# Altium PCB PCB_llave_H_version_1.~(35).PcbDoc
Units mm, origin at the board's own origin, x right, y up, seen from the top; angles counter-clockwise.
Board outline 232.16 x 155.45 mm, 2 copper layers (Top Layer, Bottom Layer); 60 components, 32 nets, 175 pads, 0 vias.
Unrouted connection lines stored in the file: 67.
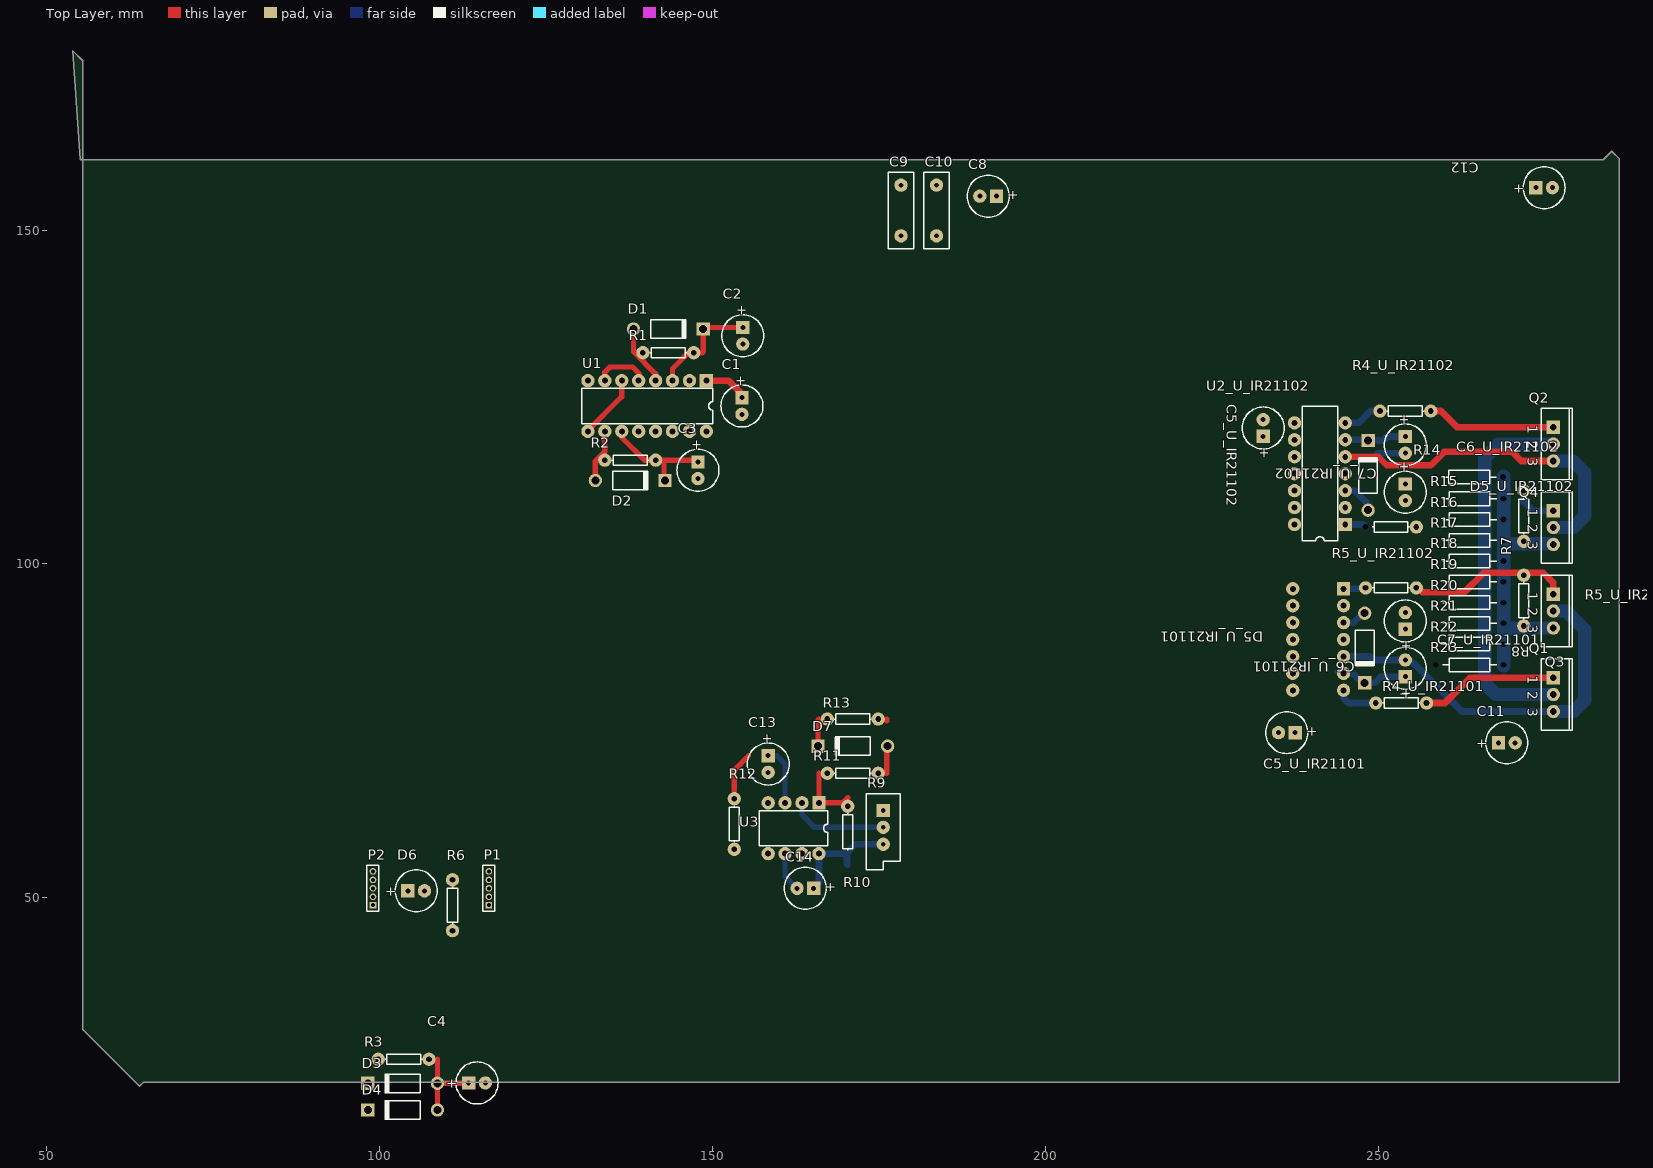
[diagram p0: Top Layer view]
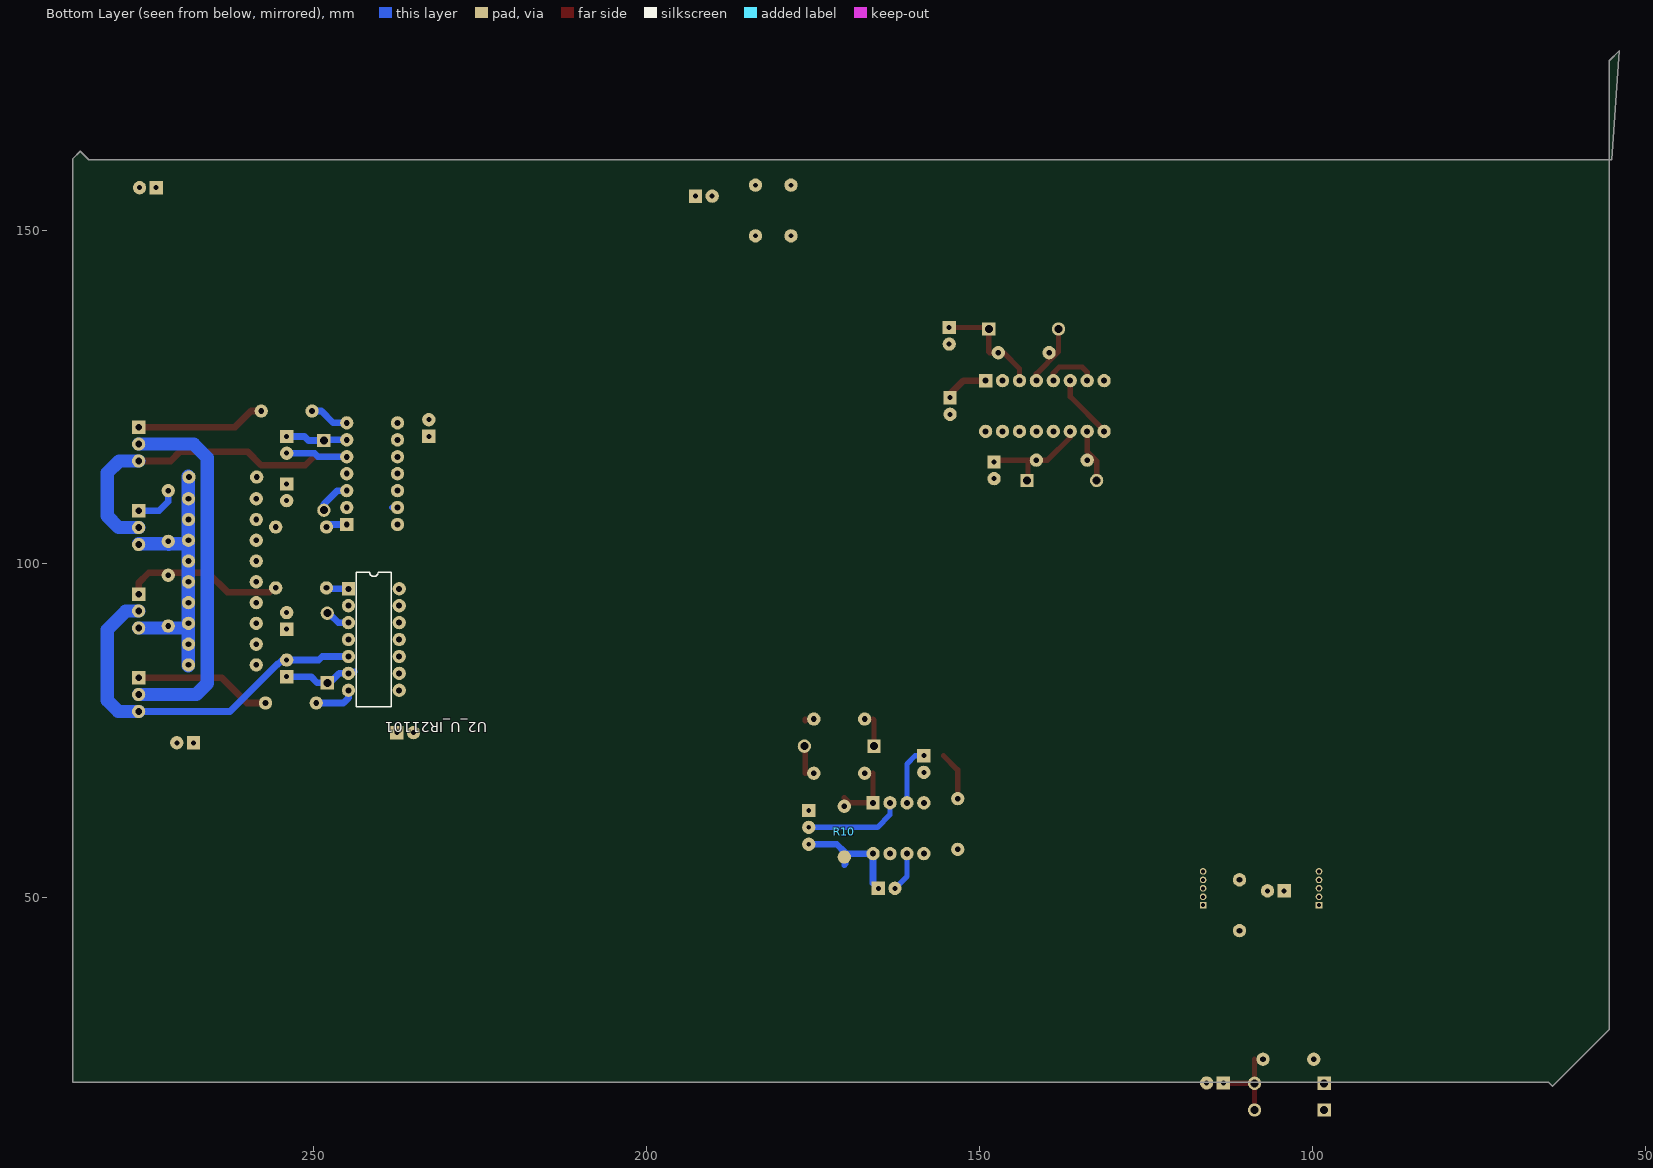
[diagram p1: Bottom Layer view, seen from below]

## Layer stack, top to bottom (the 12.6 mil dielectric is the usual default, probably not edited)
Top Layer: signal copper 0.0356
Dielectric: dielectric 0.32, FR-4, Dk 4.8
Bottom Layer: signal copper 0.0356

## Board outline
53.975,177.038 55.499,175.514 55.499,30.099 64.008,21.59 64.643,22.225 286.131,22.225 286.131,160.782 284.988,161.925 283.718,160.655 55.118,160.655

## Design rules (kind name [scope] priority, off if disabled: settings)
Clearance [All] p1: gap=0.4
ComponentClearance [All] p1: gap=0.254 collisioncheckmode=2 verticalgap=0.254
PolygonConnect [All] p1: connectstyle=Relief reliefconductorwidth=0.254 reliefentries=4 polygonreliefangle="90 Angle"
RoomDefinition U_IR21102 [InComponentClass('U_IR21102')] p1: confinementstyle=ConfineIn formatcopy=TRUE lockcomponents=FALSE outline 226.949,131.445 260.858,131.445 260.858,95.504 226.949,95.504
RoomDefinition U_Puente_H [InComponentClass('U_Puente_H')] p2: confinementstyle=ConfineOut formatcopy=TRUE lockcomponents=FALSE outline 302.133,128.016 302.133,110.363 311.531,110.363 311.531,128.016
RoomDefinition U_INITShutdown [InComponentClass('U_INITShutdown')] p3: confinementstyle=ConfineIn formatcopy=TRUE lockcomponents=FALSE outline 90.297,32.893 141.097,32.893 141.097,13.97 90.297,13.97
RoomDefinition U_Shutdown [InComponentClass('U_Shutdown')] p4: confinementstyle=ConfineOut formatcopy=TRUE lockcomponents=FALSE outline 142.113,82.931 143.51,82.931 143.51,79.629 142.113,79.629
RoomDefinition Llave_H_esquema [InComponentClass('Llave_H_esquema')] p5: confinementstyle=ConfineIn formatcopy=TRUE lockcomponents=FALSE outline 97.917,40.513 118.237,40.513 118.237,57.531 97.917,57.531
RoomDefinition U_4049 [InComponentClass('U_4049')] p6: confinementstyle=ConfineIn formatcopy=TRUE lockcomponents=FALSE outline 120.904,108.712 162.56,108.712 162.56,141.478 120.904,141.478
RoomDefinition U_IR21101 [InComponentClass('U_IR21101')] p7: confinementstyle=ConfineIn formatcopy=TRUE lockcomponents=FALSE outline 227.203,107.188 260.604,107.188 260.604,66.167 227.203,66.167
RoutingVias [All] p1: holewidth=0.711 width=1.27 viastyle="Through Hole" minholewidth=0.711 minwidth=1.27 maxholewidth=0.711 maxwidth=1.27
SolderMaskExpansion [All] p1: expansion=0.102
TestPointUsage [All] p1: valid=0 allowmultiple=FALSE
Testpoint [All] p1: side=15 testpointundercomponent=TRUE minsize=1.016 maxsize=2.54 preferedsize=1.524 minholesize=0 maxholesize=1.016 preferedholesize=0.813 testpointgrid=0.025 style=1023 order=0-112345678
Width [All] p1: maxlimit=3 minlimit=0.8 preferedwidth=1
18 further rules are at their usual default settings.

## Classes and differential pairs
component class U_INITShutdown: C4 D3 D4 R3
channel class IR2110: U_IR21101 U_IR21102
component class U_Shutdown: C13 C14 D7 R9 R10 R11 R12 R13 R14 R15 R16 R17 R18 R19 R20 R21 R22 R23 U3
component class U_Puente_H: C8 C9 C10 C11 C12 Q1 Q2 Q3 Q4 R7 R8
component class U_IR21102: C5_U_IR21102 C6_U_IR21102 C7_U_IR21102 D5_U_IR21102 R4_U_IR21102 R5_U_IR21102 U2_U_IR21102
component class U_IR21101: C5_U_IR21101 C6_U_IR21101 C7_U_IR21101 D5_U_IR21101 R4_U_IR21101 R5_U_IR21101 U2_U_IR21101
component class U_4049: C1 C2 C3 D1 D2 R1 R2 U1
component class Llave_H_esquema: D6 P1 P2 R6

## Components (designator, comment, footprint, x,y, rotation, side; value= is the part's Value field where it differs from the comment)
C1 "Cap Pol1" CAPPR2.5-6.3X5 154.432,123.698 r270 top
C2 "Cap Pol1" CAPPR2.5-6.3X5 154.559,134.239 r270 top
C3 "Cap Pol1" CAPPR2.5-6.3X5 147.828,114.046 r270 top
C4 "Cap Pol1" CAPPR2.5-6.3X5 114.681,22.098 r0 top
C5_U_IR21101 "Cap Pol1" CAPPR2.5-6.3X5 236.22,74.676 r180 top (schematic designator C5)
C5_U_IR21102 "Cap Pol1" CAPPR2.5-6.3X5 232.664,120.396 r90 top (schematic designator C5)
C6_U_IR21101 "Cap Pol1" CAPPR2.5-6.3X5 254,84.328 r90 top (schematic designator C6)
C6_U_IR21102 "Cap Pol1" CAPPR2.5-6.3X5 254,117.856 r270 top (schematic designator C6)
C7_U_IR21101 "Cap Pol1" CAPPR2.5-6.3X5 254,91.44 r90 top (schematic designator C7)
C7_U_IR21102 "Cap Pol1" CAPPR2.5-6.3X5 254,110.744 r270 top (schematic designator C7)
C8 "Cap Pol1" CAPPR2.5-6.3X5 191.389,155.194 r180 top
C9 "Cap" RAD-0.3 178.308,153.035 r90 top
C10 "Cap" RAD-0.3 183.642,153.035 r90 top
C11 "Cap Pol1" CAPPR2.5-6.3X5 269.24,73.152 r0 top
C12 "Cap Pol1" CAPPR2.5-6.3X5 274.828,156.464 r0 top
C13 "Cap Pol1" CAPPR2.5-6.3X5 158.369,69.957 r270 top
C14 "Cap Pol1" CAPPR2.5-6.3X5 163.957,51.308 r180 top
D1 "Diode" DO-204AL 143.383,135.255 r0 top
D2 "Diode" DO-204AL 137.668,112.522 r0 top
D3 "Diode" DO-204AL 103.505,22.036 r180 top
D4 "Diode" DO-204AL 103.505,18.034 r180 top
D5_U_IR21101 "Diode" DO-204AL 247.904,87.376 r270 top (schematic designator D5)
D5_U_IR21102 "Diode" DO-204AL 248.412,113.284 r90 top (schematic designator D5)
D6 "LED0" CAPPR2.5-6.3X5 105.537,50.927 r0 top
D7 "Diode" DO-204AL 171.069,72.644 r180 top
P1 "MHDR1X5" MHDR1X5 116.459,48.768 r90 top
P2 "MHDR1X5" MHDR1X5 99.06,48.768 r90 top
Q1 "IRF3205" TO-220AB 276.225,80.391 r270 top
Q2 "IRF3205" TO-220AB 276.225,117.983 r270 top
Q3 "IRF3205" TO-220AB 276.225,92.922 r270 top
Q4 "IRF3205" TO-220AB 276.225,105.452 r270 top
R1 "Res2" AXIAL-0.3#1 143.383,131.699 r180 top
R2 "Res2" AXIAL-0.3#1 137.668,115.57 r0 top
R3 "Res2" AXIAL-0.3#1 103.661,25.654 r180 top
R4_U_IR21101 "Res2" AXIAL-0.3#1 253.365,79.121 r0 top (schematic designator R4)
R4_U_IR21102 "Res2" AXIAL-0.3#1 254,122.936 r0 top (schematic designator R4)
R5_U_IR21101 "Res2" AXIAL-0.3#1 251.841,96.393 r0 top (schematic designator R5)
R5_U_IR21102 "Res2" AXIAL-0.3#2 251.841,105.537 r0 top (schematic designator R5)
R6 "Res2" AXIAL-0.3#1 110.998,48.768 r90 top
R7 "Res2" AXIAL-0.3#1 271.78,107.188 r90 top
R8 "Res2" AXIAL-0.3#3 271.78,94.488 r90 top
R9 "RPot" VR5 175.641,60.452 r270 top
R10 "Res2" AXIAL-0.3#4 170.307,59.817 r270 top
R11 "Res2" AXIAL-0.3#1 171.069,68.58 r0 top
R12 "Res2" AXIAL-0.3#1 153.289,60.96 r90 top
R13 "Res2" AXIAL-0.3#1 171.069,76.708 r180 top
R14 "Res2" AXIAL-0.4#1 263.585,113.03 r0 top
R15 "Res2" AXIAL-0.4#1 263.652,109.774 r0 top
R16 "Res2" AXIAL-0.4#1 263.652,106.657 r0 top
R17 "Res2" AXIAL-0.4#1 263.652,103.539 r0 top
R18 "Res2" AXIAL-0.4#1 263.652,100.422 r0 top
R19 "Res2" AXIAL-0.4#1 263.652,97.305 r0 top
R20 "Res2" AXIAL-0.4#2 263.652,94.188 r0 top
R21 "Res2" AXIAL-0.4#2 263.652,91.07 r0 top
R22 "Res2" AXIAL-0.4#2 263.652,87.953 r0 top
R23 "Res2" AXIAL-0.4#2 263.652,84.836 r0 top
U1 "MC54HC4049J" 620-09 140.208,123.698 r180 top
U2_U_IR21101 "IR2110" PDIP14 240.919,88.646 r270 bottom (schematic designator U2)
U2_U_IR21102 "IR2110" PDIP14 241.173,113.538 r90 top (schematic designator U2)
U3 "LM393N" 626-05 162.179,60.325 r180 top

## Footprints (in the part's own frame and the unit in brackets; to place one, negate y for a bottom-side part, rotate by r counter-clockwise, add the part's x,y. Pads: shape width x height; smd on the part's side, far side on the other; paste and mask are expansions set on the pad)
620-09 [mm] "DIP; 16 Leads; Row Spacing 7.62 mm; Pitch 2.54 mm"
  rect 2x2 hole 0.9: 1(-8.89,-3.81)
  round 2 hole 0.9: 2(-6.35,-3.81) 3(-3.81,-3.81) 4(-1.27,-3.81) 5(1.27,-3.81) 6(3.81,-3.81) 7(6.35,-3.81) 8(8.89,-3.81) 9(8.89,3.81) 10(6.35,3.81) 11(3.81,3.81) 12(1.27,3.81) 13(-1.27,3.81) 14(-3.81,3.81) 15(-6.35,3.81) 16(-8.89,3.81)
  silkscreen extent -9.85,-2.65 9.85,2.65
626-05 [mm] "DIP; 8 Leads; Row Spacing 7.62 mm; Pitch 2.54 mm"
  rect 2x2 hole 0.9: 1(-3.81,-3.81)
  round 2 hole 0.9: 2(-1.27,-3.81) 3(1.27,-3.81) 4(3.81,-3.81) 5(3.81,3.81) 6(1.27,3.81) 7(-1.27,3.81) 8(-3.81,3.81)
  silkscreen extent -5.15,-2.65 5.15,2.65
AXIAL-0.3#1 [mm] "Resistor; 2 Leads"
  round 2 hole 0.85: 1(-3.81,0) 2(3.81,0)
  silkscreen extent -2.77,-0.76 2.77,0.76
AXIAL-0.3#2 [mm] "Resistor; 2 Leads"
  round 0 / inner round 0 / far side round 2 hole 0.85: 1(-3.81,0)
  round 2 hole 0.85: 2(3.81,0)
  silkscreen extent -2.77,-0.76 2.77,0.76
AXIAL-0.3#3 [mm] "Resistor; 2 Leads"
  round 2 hole 0.85 paste+0 mask+0.102: 1(-3.81,0)
  round 2 hole 0.85: 2(3.81,0)
  silkscreen extent -2.77,-0.76 2.77,0.76
AXIAL-0.3#4 [mm] "Resistor; 2 Leads"
  round 2 hole 0.85: 1(-3.81,0)
  round 2 smd far side: 2(3.81,0)
  silkscreen extent -2.77,-0.76 2.77,0.76
AXIAL-0.4#1 [mm] "Resistor; 2 Leads"
  round 0 / inner round 0 / far side round 2 hole 0.85: 1(-5.08,0) 2(5.08,0)
  silkscreen extent -4.06,-1.02 4.06,1.02
AXIAL-0.4#2 [mm] "Resistor; 2 Leads"
  round 0 / inner round 0 / far side round 2 hole 0.85: 1(-5.08,0)
  round 0 / inner round 0 / far side round 2 hole 0.85 unplated: 2(5.08,0)
  silkscreen extent -4.06,-1.02 4.06,1.02
CAPPR2.5-6.3X5 [mm] "Capacitor, Electrolytic, Radial; Body 6.3 x 5 mm (Dia.xH typ); Pin Spacing 2.5 mm (typ)"
  rect 2x2 hole 0.75: 1(-1.25,0)
  round 2 hole 0.75: 2(1.25,0)
  silkscreen extent -3.15,-3.15 3.15,3.15
DO-204AL [mm] "Diode, Axial; Body 5.2 x 2.7 mm (LxDia. max), Lead Dia. 0.86 mm (max)"
  round 2 hole 1.2: 1(-5.23,0)
  rect 2x2 hole 1.2: 2(5.23,0)
  silkscreen extent -2.65,-1.4 2.75,1.4
MHDR1X5 [mm] "Connector; Header; 5 Position"
  rect 1x1 hole 0.6: 1(0,0)
  round 1 hole 0.6: 2(1.27,0) 3(2.54,0) 4(3.81,0) 5(5.08,0)
  silkscreen extent -0.9,-0.9 5.98,0.9
PDIP14 [mm] "DIP; 14 Leads; Row Spacing 7.62 mm; Pitch 2.54 mm"
  rect 2x2 hole 0.9: 1(-7.62,-3.81)
  round 2 hole 0.9: 2(-5.08,-3.81) 3(-2.54,-3.81) 4(0,-3.81) 5(2.54,-3.81) 6(5.08,-3.81) 7(7.62,-3.81) 8(7.62,3.81) 9(5.08,3.81) 10(2.54,3.81) 11(0,3.81) 12(-2.54,3.81) 13(-5.08,3.81) 14(-7.62,3.81)
  silkscreen extent -10.1,-2.65 10.1,2.65
RAD-0.3 [mm] "Capacitor; 2 Leads"
  round 2 hole 0.7: 1(-3.81,0) 2(3.81,0)
  silkscreen extent -5.71,-1.91 5.71,1.91
TO-220AB [mm] "TO, Thru-Hole, Vertical, Heatsink Mounted; 3 In-Line Leads; Pitch 2.54 mm"
  rect 2x2 hole 1: 1(-2.54,0)
  round 2 hole 1: 2(0,0) 3(2.54,0)
  silkscreen extent -5.35,-1.85 5.35,2.85
VR5 [mm] "Potentiometer; 3 Leads"
  rect 2x2 hole 0.7: 1(-2.54,0)
  round 2 hole 0.7: 2(2.54,0) 3(0,0)
  silkscreen extent -5.08,-2.54 6.35,2.54

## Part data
C1 C2 C3 C4 C5_U_IR21101 C5_U_IR21102 C6_U_IR21101 C6_U_IR21102 C7_U_IR21101 C7_U_IR21102 C8 C11 C12 C13 C14: "Polarized Capacitor (Radial)"
C9 C10: "Capacitor"
D1 D2 D3 D4 D5_U_IR21101 D5_U_IR21102 D7: "Default Diode"
D6: "Typical INFRARED GaAs LED"
P1 P2: "Header, 5-Pin"
Q1 Q2 Q3 Q4: "HEXFET Power MOSFET"
R1 R2 R3 R4_U_IR21101 R4_U_IR21102 R5_U_IR21101 R5_U_IR21102 R6 R7 R8 R10 R11 R12 R13 R14 R15 R16 R17 R18 R19 R20 R21 R22 R23: "Resistor"
R9: "Potentiometer"
U1: "Hex Inverting Buffer/Logic-Level Down Converter"
U2_U_IR21101 U2_U_IR21102: "High and Low Side Driver"
U3: "Dual Comparator"

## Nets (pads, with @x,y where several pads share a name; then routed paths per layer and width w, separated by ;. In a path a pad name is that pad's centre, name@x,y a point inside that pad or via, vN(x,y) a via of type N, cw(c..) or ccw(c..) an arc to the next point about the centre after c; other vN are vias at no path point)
COM_U_IR21101: C7_U_IR21101.2 C7_U_IR21102.2 C11.2 C12.2 Q3.3 Q4.3 R7.1 R8.1 R12.1 R14.2 R15.2 R16.2 R17.2 R18.2 R19.2 R20.2 R21.2 R22.2 R23.2 U2_U_IR21101.2 U2_U_IR21102.2 | length 47.9
  Bottom Layer w1: R7.1@271.713,102.997 271.798,102.912 Q4.3
  Bottom Layer w2: R23.2@268.792,84.709 R14.2@268.792,113.157 ; R21.2@268.792,90.382 Q3.3 ; R17.2@268.792,103.031 Q4.3@276.191,103.031 ; R7.1@271.713,102.965 R7.1@271.78,103.031
GND: C1.2 C2.2 C3.2 C4.2 C5_U_IR21101.2 C5_U_IR21102.2 C8.2 C9.1 C10.1 C13.2 C14.2 D6.2 P1.1 P2.4 R9.1 R13.1 R14.1 R15.1 R16.1 R17.1 R18.1 R19.1 R20.1 R21.1 R22.1 R23.1 U1.8 U2_U_IR21101.13 U2_U_IR21102.13 U3.4 U3.5 U3.6 | length 7.2
  Top Layer w0.8: U3.5 158.389,56.535 U3.5@158.369,56.555 ; U3.6@160.889,56.535 U3.6 ; 176.149,76.454 176.149,76.708
  Bottom Layer w0.8: U3.6 160.909,53.106 C14.2 ; U2_U_IR21102.13 U2_U_IR21102.13@238.252,108.458
HIN_U_IR21101: U1.12 U2_U_IR21101.10 U2_U_IR21102.12
HIN_U_IR21102: U1.2 U2_U_IR21101.12 U2_U_IR21102.10
HO1: Q2.1 R4_U_IR21102.2 | length 19.4
  Top Layer w1: R4_U_IR21102.2 259.334,122.936 261.747,120.523 Q2.1
HO2: Q1.1 R4_U_IR21101.2 | length 20.6
  Top Layer w1: R4_U_IR21101.2 259.969,79.121 263.779,82.931 Q1.1
IN_SD: D4.2 P2.3
LO1: Q4.1 R5_U_IR21102.2 R7.2 | length 6.7
  Bottom Layer w1: R7.2 271.78,109.347 273.135,107.992 Q4.1
LO2: Q3.1 R5_U_IR21101.2 R8.2 | length 25.1
  Top Layer w1: R5_U_IR21101.2 255.905,96.393 256.54,95.758 262.89,95.758 265.811,98.679 274.701,98.679 276.225,97.155 Q3.1 ; R8.2@271.526,98.679 R8.2@271.78,98.425
  Bottom Layer w1: R5_U_IR21101.2 R5_U_IR21101.2@256.032,96.393
MOTOR+: C6_U_IR21102.2 Q2.3 Q4.2 U2_U_IR21102.5 | length 59.8
  Top Layer w1: U2_U_IR21102.5 249.936,116.078 251.206,114.808 257.836,114.808 259.868,116.84 270.002,116.84 271.399,115.443 Q2.3
  Bottom Layer w1: U2_U_IR21102.5 249.301,116.078 249.829,116.606 C6_U_IR21102.2
  Bottom Layer w2: Q4.2 279.188,105.452 280.924,107.188 280.924,113.665 279.146,115.443 Q2.3
MOTOR-: C6_U_IR21101.2 Q1.3 Q3.2 U2_U_IR21101.5 | length 56.8
  Bottom Layer w1: U2_U_IR21101.5 248.666,86.106 249.194,85.578 254.655,85.578 255.255,84.978 255.382,84.978 262.509,77.851 Q1.3
  Bottom Layer w2: Q1.3 279.273,77.851 280.924,79.502 280.924,90.128 278.13,92.922 Q3.2
NetC2_1: C2.1 D1.2 R1.1 U1.3 | length 16.9
  Top Layer w0.8: U1.3 144.018,129.286 146.431,131.699 148.463,131.699 148.613,131.849 D1.2 148.847,135.489 C2.1
NetC3_1: C3.1 D2.2 R2.2 U1.11 | length 17
  Top Layer w0.8: U1.11 136.398,118.999 139.827,115.57 147.554,115.57 C3.1 ; 142.748,115.57 142.748,112.672 D2.2
NetC4_1: C4.1 D3.1 D4.1 R3.1 | length 12.8
  Top Layer w0.8: D3.1@108.429,22.342 D3.1 113.369,22.036 C4.1 ; D4.1 108.741,18.04 108.741,25.654
NetC6_U_IR21101_1: C6_U_IR21101.1 D5_U_IR21101.2 U2_U_IR21101.6 | length 10.8
  Bottom Layer w1: U2_U_IR21101.6@243.84,83.82 U2_U_IR21101.6@244.602,83.82 ; U2_U_IR21101.6 246.126,83.566 D5_U_IR21101.2@247.673,82.019 ; D5_U_IR21101.2 249.405,82.146 250.337,83.078 C6_U_IR21101.1
NetC6_U_IR21102_1: C6_U_IR21102.1 D5_U_IR21102.2 U2_U_IR21102.6 | length 9.8
  Bottom Layer w1: U2_U_IR21102.6 248.308,118.618 D5_U_IR21102.2 250.721,118.514 251.313,119.106 C6_U_IR21102.1 ; D5_U_IR21102.2@248.943,118.872 D5_U_IR21102.2@249.301,118.514
NetC13_1: C13.1 R12.2 U3.3 | length 15.1
  Top Layer w0.8: 153.289,66.04 153.289,69.088 155.408,71.207 ; C13.1 C13.1@158.456,71.12
  Bottom Layer w0.8: C13.1 159.679,71.207 160.909,69.977 U3.3
NetD1_1: D1.1 R1.2 U1.4 | length 9.1
  Top Layer w0.8: D1.1 138.153,131.849 141.478,128.524 U1.4
NetD2_1: D2.1 R2.1 U1.10 | length 8
  Top Layer w0.8: D2.1 132.438,115.42 133.858,116.84 U1.10
NetD6_1: D6.1 R6.1
NetD7_1: D7.1 R11.2 | length 4.2
  Top Layer w0.8: 176.149,68.58 D7.1@176.149,72.771
NetR4_U_IR21101_1: R4_U_IR21101.1 U2_U_IR21101.7 | length 6.3
  Bottom Layer w1: U2_U_IR21101.7 244.729,79.883 245.491,79.121 R4_U_IR21101.1
NetR4_U_IR21102_1: R4_U_IR21102.1 U2_U_IR21102.7 | length 5.9
  Bottom Layer w1: U2_U_IR21102.7 247.015,121.158 248.793,122.936 R4_U_IR21102.1
NetR5_U_IR21101_1: R5_U_IR21101.1 U2_U_IR21101.1 | length 3.2
  Bottom Layer w1: U2_U_IR21101.1 R5_U_IR21101.1@247.904,96.266
NetR5_U_IR21102_1: R5_U_IR21102.1 U2_U_IR21102.1 | length 3.2
  Bottom Layer w1: U2_U_IR21102.1 247.65,105.918 R5_U_IR21102.1
NetR9_3: R9.3 U3.2 | length 14.8
  Bottom Layer w0.8: U3.2 163.449,62.357 165.354,60.452 R9.3
NetR10_1: R10.1 R11.1 U3.1 | length 9.1
  Top Layer w0.8: 165.989,68.58 U3.1 169.545,64.135 170.307,64.897
NetU1_6: U1.6 U1.9 | length 9.7
  Top Layer w0.8: U1.9 131.318,120.015 136.398,125.095 U1.6
PWM: P2.2 U1.5 U1.7 | length 8.2
  Top Layer w0.8: U1.7 133.858,128.778 134.62,129.54 138.049,129.54 138.938,128.651 U1.5
SD: D3.2 D7.2 R13.2 U2_U_IR21101.11 U2_U_IR21102.11 | length 4.1
  Top Layer w0.8: D7.2 165.839,76.558 165.989,76.708
VCC_MOTOR: C8.1 C9.2 C10.2 C11.1 C12.1 P1.2 Q1.2 Q2.2 | length 56
  Bottom Layer w2: Q1.2 267.589,80.391 265.938,82.042 265.938,115.951 267.97,117.983 Q2.2
VDD: C1.1 C5_U_IR21101.1 C5_U_IR21102.1 C7_U_IR21101.1 C7_U_IR21102.1 C14.1 D5_U_IR21101.1 D5_U_IR21102.1 P2.5 R3.2 R6.2 R9.2 R10.2 U1.1 U2_U_IR21101.3 U2_U_IR21101.9 U2_U_IR21102.3 U2_U_IR21102.9 U3.8 | length 35.9
  Top Layer w0.8: C1.1 C1.1@154.432,125.349 ; C14.1 C14.1@165.207,51.923 ; U3.8@165.862,56.769 165.989,56.642 U3.8
  Top Layer w1: U1.1 152.4,127.508 154.432,125.476 C1.1
  Bottom Layer w0.8: R10.2@170.053,56.515 170.053,54.991 170.307,54.737 170.307,56.734 R10.2@170.289,56.751
  Bottom Layer w1: C14.1 165.989,52.09 U3.8 R10.2@170.053,56.515 ; R10.2@170.289,56.751 171.45,57.912 R9.2 ; U2_U_IR21101.3 246.253,91.186 D5_U_IR21101.1@247.546,92.479 ; U2_U_IR21102.3 246.38,110.998 248.412,108.966 D5_U_IR21102.1
pads on no net: P1.3 P1.4 P1.5 P2.1 U1.13 U1.14 U1.15 U1.16 U2_U_IR21101.4 U2_U_IR21101.8 U2_U_IR21101.14 U2_U_IR21102.4 U2_U_IR21102.8 U2_U_IR21102.14 U3.7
